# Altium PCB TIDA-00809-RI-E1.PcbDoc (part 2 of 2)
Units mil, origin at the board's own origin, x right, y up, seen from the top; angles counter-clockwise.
Board outline 5400 x 1000 mil, 2 copper layers (Top Layer, Bottom Layer), stack 62 mil thick; 167 components, 75 nets, 354 pads, 72 vias.
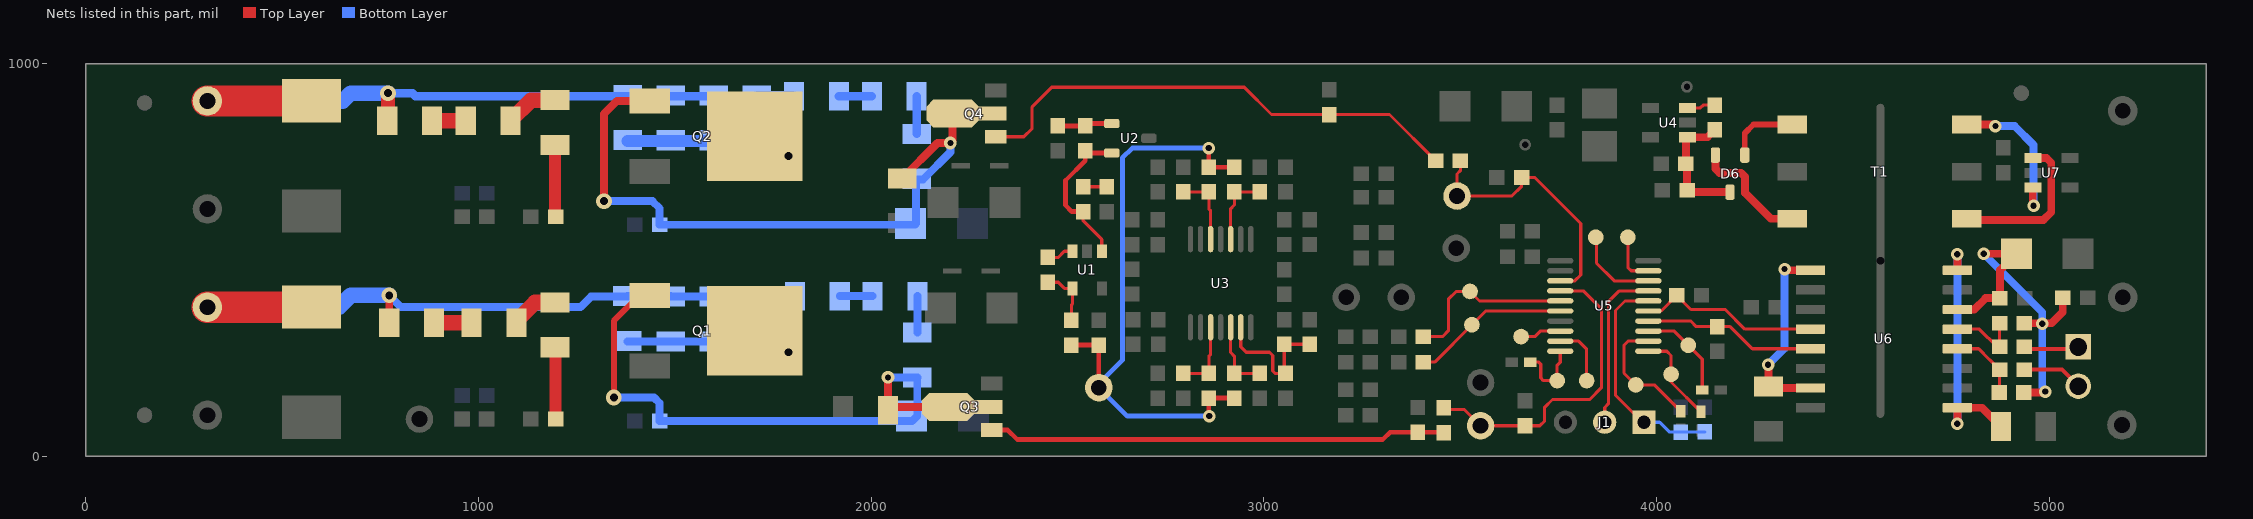
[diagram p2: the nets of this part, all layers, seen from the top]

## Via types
v1: diameter 32, hole 16, Top Layer to Bottom Layer, tented both sides, 61 vias
v2: diameter 40, hole 20, Top Layer to Bottom Layer, tented both sides, 11 vias

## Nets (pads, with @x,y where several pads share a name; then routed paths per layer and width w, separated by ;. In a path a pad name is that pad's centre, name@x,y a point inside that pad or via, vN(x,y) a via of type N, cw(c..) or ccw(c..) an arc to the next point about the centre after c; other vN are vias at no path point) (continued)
NetC7_2: C7.2 R32.2 R34.2 U3.13 | length 355
  Top Layer w8: U3.13@2941.18,328.78 2941.18,278.82 2955,265 3014.43,265 3022.7,256.73 3022.7,217.3 3028.5,211.5 R34.2@3055,211.5 3052,214.5 R32.2@3052,285.5 C7.2@3117,285.5
NetC21_1: C21.1 J1.1 R60.1 U5.16 | length 585.2
  Top Layer w8: J1.1@3973,78 3966,85 3895.5,155.5 3895.5,371.5 3919.8,395.8 U5.16@3979.2,395.8
  Bottom Layer w8: J1.1@3968,87 4008,87 4033.31,61.69 C21.1@4061.3,61.69 4062.11,62.5 R60.1@4123,62.5
NetC22_2: C22.2 D8.1 Q2.G Q4.2 Q4.4 R12.2 R62.2 | length 1688.1
  Top Layer w20: v2(1320,650) 1320,872.13 1352.64,904.76 Q2.G@1436.14,904.76 ; R12.2@2079,708.09 2168.91,798 v1(2202,798) 2207.57,803.57 Q4.4@2207.57,873
  Bottom Layer w12: D8.1@2114.51,593 D8.1@2116,594.49
  Bottom Layer w20: v2(1320,650) 1443,650 1461.5,631.5 C22.2@1461.5,590 2111.51,590 2114.51,593 2114.51,705.42 2132.42,705.42 2202,775 v1(2202,798)
NetC23_2: C23.2 D7.1 Q1.G Q3.2 Q3.4 R11.2 R61.1 | length 1591.1
  Top Layer w15: v2(1345,150) 1345,345 1409.76,409.76 Q1.G@1436.14,409.76
  Top Layer w20: v1(2043,201) 2043.09,200.91 R11.2@2043.09,117 2052.09,126 Q3.4@2196.57,126 ; Q3.4@2170,135 Q3.4@2204.57,135
  Bottom Layer w20: v2(1345,150) 1447,150 1461.5,135.5 C23.2@1461.5,90 2104.53,90 2117.53,103 R61.1@2117.53,200.44 ; v1(2043,201) 2116.98,201 R61.1@2117.53,200.44 ; R61.1@2118,200.91 R61.1@2117.53,200.44
NetD1_2: D1.2 R1.1 R66.1 R67.2 R70.2 R71.2 R73.2 TP1.1 | length 1850.3
  Top Layer w22: R1.1@767.91,855 R1.1@770,857.09 ; R1.1@772.91,860 R1.1@777.91,855
  Top Layer w35: R1.1@770,857.09 v2(770,925)
  Top Layer w80: TP1.1@310,905 574.51,905 D1.2@575,905.49
  Bottom Layer w22: v2(770,925) 832.09,925 840,917.09 1707,917.09 R67.2@1709,919.09 1801.83,919.09 R66.1@1803.91,917
  Bottom Layer w40: TP1.1@310,905 655,905 675,925 v2(770,925)
NetD2_2: D2.2 R2.1 R65.1 R68.2 R69.2 R72.2 R74.2 TP3.1 | length 1979.1
  Top Layer w20: R2.1@772.91,340 v2(772.91,410)
  Top Layer w80: TP3.1@310,380 574.51,380 D2.2@575,380.49
  Bottom Layer w20: v2(772.91,410) 802.91,380 1260,380 1287.09,407.09 R72.2@1490,407.09 ; R74.2@1379,408.09 1489,408.09 R72.2@1490,407.09 ; R65.1@1805.91,408 1805.83,408.09 R68.2@1709,408.09 1708,407.09 R69.2@1600,407.09 R72.2@1490,407.09
  Bottom Layer w40: TP3.1@310,380 645,380 675,410 v2(772.91,410)
NetD6_1: D6.1 T1.4 | length 185.6
  Top Layer w15: D6.1@4224.72,767.27 4224.72,823 4246.72,845 T1.4@4345.5,845
NetD6_2: D6.2 T1.6 | length 307.2
  Top Layer w20: D6.2@4149.91,767.27 4149.91,732.43 4160.32,722.02 4215.32,722.02 4225.32,712.02 4225.32,671.02 4291.34,605 T1.6@4345.5,605
NetJ1_2: J1.2 U5.17 | length 430.1
  Top Layer w8: J1.2@3868,87 3868,124.5 3877.5,134 3877.5,393.5 3905.39,421.39 U5.17@3979.2,421.39 ; J1.2@3873,78 J1.2@3877.5,82.5
NetL1_2: L1.2 U6.1 U6.7 | length 492.6
  Top Layer w20: v1(4284,233) 4285,232 L1.2@4285,178.09 4289.09,174 U6.7@4391.99,174 ; v1(4326,477) 4329,474 U6.1@4391.99,474
  Bottom Layer w20: v1(4284,233) 4326,275 v1(4326,477)
NetL2_1: L2.1 U6.9 U6.16 | length 650.9
  Top Layer w20: v1(4766,83) U6.9@4766.01,124 4828.91,124 L2.1@4876.91,76 L2.1@4876.91,82.09 ; U6.16@4766.01,474 v1(4766,515)
  Bottom Layer w20: v1(4766,83) v1(4766,515)
NetQ1_D: Q1.D R68.1 R69.1 R72.1 R74.1 | length 421.6
  Bottom Layer w20: R74.1@1380,292.91 R72.1@1490,292.91 R69.1@1600,292.91 1710,292.91 1762.09,292.91 v2(1790,265)
NetQ2_D: Q2.D R67.1 R70.1 R71.1 R73.1 | length 532.6
  Top Layer w30: Q2.D@1703.86,815 1753.86,765 v2(1790,765)
  Bottom Layer w30: R73.1@1380,802.91 1490,802.91 1600,802.91 1710,802.91 1747.91,765 v2(1790,765)
NetQ3_1: Q3.1 R42.2 R44.2 | length 1169.2
  Top Layer w12: Q3.1@2306.8,66.94 2348.06,66.94 2372.03,42.97 3302.97,42.97 3321.5,61.5 R42.2@3392,61.5 3457,61.5 R44.2@3458,60.5
NetQ4_1: Q4.1 R35.2 R43.2 | length 1281.6
  Top Layer w8: Q4.1@2317.8,813.94 2388.94,813.94 2410,835 2410,890 2460,940 2950,940 3019.5,870.5 R35.2@3167,870.5 3320,870.5 R43.2@3437.5,753
NetR1_2: R1.2 R5.1 | length 85.8
  Top Layer w40: R1.2@882.09,855 R5.1@967.91,855
NetR2_2: R2.2 R6.1 | length 95.8
  Top Layer w40: R2.2@887.09,340 R6.1@982.91,340
NetR5_2: R5.2 R9.1 | length 134.5
  Top Layer w40: R5.2@1082.09,855 1134.17,907.09 R9.1@1195,907.09
NetR6_2: R6.2 R10.1 | length 117.4
  Top Layer w40: R6.2@1097.09,345 1144.17,392.09 R10.1@1195,392.09
NetR7_1: R7.1 R9.2 | length 183.5
  Top Layer w30: R9.2@1195,792.91 1195,611.5 R7.1@1196.5,610
NetR8_1: R8.1 R10.2 | length 183.5
  Top Layer w30: R10.2@1195,277.91 1196.5,276.42 R8.1@1196.5,95
NetR13_1: R13.1 U1.3 | length 69.1
  Top Layer w8: R13.1@2450,506.5 2476.5,506.5 2492.24,522.24 U1.3@2512.6,522.24
NetR13_2: R13.2 R15.1 U1.4 | length 151.5
  Top Layer w8: R13.2@2450,443.5 2476.5,443.5 2492.24,427.76 U1.4@2512.6,427.76 2512.6,387.6 2510,385 R15.1@2510,346.5
NetR14_2: R14.2 R17.1 U2.1 | length 140.2
  Top Layer w12: R14.2@2475,841.5 R17.1@2545,841.5 2550.91,847.4 U2.1@2612.76,847.4
NetR16_1: R16.1 R17.2 U1.1 U2.2 | length 402.1
  Top Layer w8: R16.1@2540,623.5 2540,600 2587.4,552.6 U1.1@2587.4,522.24
  Top Layer w12: R16.1@2540,623.5 2511.5,623.5 2495,640 2495,702.51 2545,752.51 R17.2@2545,778.5 2550.91,772.6 U2.2@2612.76,772.6
NetR16_2: R16.2 R18.2 | length 60
  Top Layer w8: R16.2@2540,686.5 R18.2@2600,686.5
NetR23_2: R23.2 R25.2 U3.10 | length 184.1
  Top Layer w8: R23.2@2795,211.5 R25.2@2860,211.5 2860,255 2864.41,259.41 U3.10@2864.41,328.78
NetR24_2: R24.2 R26.2 U3.5 | length 187.1
  Top Layer w8: R24.2@2795,673.5 R26.2@2860,673.5 2860,630 2864.41,625.59 U3.5@2864.41,553.19
NetR27_2: R27.2 R30.2 U3.12 | length 186.2
  Top Layer w8: U3.12@2915.59,328.78 2915.59,264.41 2925,255 R27.2@2925,211.5 R30.2@2990,211.5
NetR28_2: R28.2 R29.1 U3.3 | length 189.2
  Top Layer w8: U3.3@2915.59,553.19 2915.59,630.59 2925,640 R28.2@2925,673.5 R29.1@2990,673.5
NetR40_2: R40.2 TP12.1 U5.5 | length 452.8
  Top Layer w8: R40.2@3406.5,305 3455,305 3470,320 3470,400 3490,420 TP12.1@3525,420 3549.2,395.8 U5.5@3754.8,395.8
NetR41_2: R41.2 TP13.1 U5.6 | length 402.2
  Top Layer w8: R41.2@3406.5,240 3435,240 TP13.1@3530,335 3565.2,370.2 U5.6@3754.8,370.2
NetR46_2: R46.2 TP17.1 U5.10 | length 186.6
  Top Layer w8: R46.2@3678.62,240 3700,240 3705,235 3705,200 3712,193 TP17.1@3747,193 3747,232 3754.8,239.8 U5.10@3754.8,267.84 ; U5.10@3747,267.84 U5.10@3747,268
NetR48_1: R48.1 U4.3 | length 72.7
  Top Layer w8: U4.3@4078.56,887.43 4111.52,887.43 4118.61,894.52 R48.1@4148.32,894.52
NetR50_2: R50.2 TP22.1 U5.12 | length 330.1
  Top Layer w8: TP22.1@3947,182 TP22.1@3951.85,182 ; U5.12@3979.2,293.43 3927.43,293.43 3917,283 3917,212 3941,188 3945.85,188 TP22.1@3951.85,182 ; R50.2@4062,114.62 3994.62,182 TP22.1@3951.85,182 ; R50.2@4062.31,114.93 R50.2@4064,113.24
NetR51_2: R51.2 TP24.1 U5.13 | length 245.4
  Top Layer w8: U5.13@3979.2,319.02 4044.98,319.02 TP24.1@4081,283 4116.38,247.62 R51.2@4116.38,169
NetR53_2: R53.2 TP23.1 U5.11 | length 237.5
  Top Layer w8: U5.11@3979.2,267.84 4026.16,267.84 4037,257 TP23.1@4037,209 4037,189.24 R53.2@4113,113.24
NetR54_1: R54.1 R55.1 U6.13 | length 186.2
  Top Layer w8: U6.13@4766.01,324 4822,324 4867.16,278.84 R55.1@4873.5,278.84 R54.1@4873.5,338.84
NetR56_1: R56.1 R57.1 U6.12 | length 187.9
  Top Layer w8: U6.12@4766.01,274 4820.16,274 4848.02,246.14 4848.2,246.14 R56.1@4873.5,220.84 4873.5,163.84 R57.1@4872.5,162.84
NetR61_2: R61.2 R63.1 | length 92.9
  Bottom Layer w20: R61.2@2118,315.09 2118.09,315.17 R63.1@2118.09,408
NetR62_1: R62.1 R64.2 | length 95.9
  Bottom Layer w22: R62.1@2116,821.09 2116.09,821.17 R64.2@2116.09,917
NetR63_2: R63.2 R65.2 | length 83.8
  Bottom Layer w20: R65.2@1920.09,408 R63.2@2003.91,408
NetR64_1: R64.1 R66.2 | length 83.8
  Bottom Layer w22: R66.2@1918.09,917 R64.1@2001.91,917
NetT1_1: T1.1 U7.1 | length 401.7
  Top Layer w20: T1.1@4790.5,605 4793.5,602 4985,602 5005,622 5005,747.83 4993.43,759.4 U7.1@4958,759.4
NetT1_3: T1.3 U7.3 | length 393.5
  Top Layer w20: T1.3@4790.5,845 4859,845 v1(4863,841) ; U7.3@4958,684.6 4958,640 v1(4960,638)
  Bottom Layer w20: v1(4863,841) 4912,841 4960,793 v1(4960,638)
NetTP16_1: TP16.1 U5.8 | length 105.6
  Top Layer w8: TP16.1@3655,305 3690,305 3704.02,319.02 U5.8@3754.8,319.02
NetTP18_1: TP18.1 U5.9 | length 155.7
  Top Layer w8: U5.9@3754.8,293.43 3801.57,293.43 3822,273 TP18.1@3822,193
NetTP19_1: TP19.1 U5.18 | length 216.9
  Top Layer w8: TP19.1@3847,558 3847,491.98 3892,446.98 U5.18@3979.2,446.98
NetTP21_1: TP21.1 U5.19 | length 132.7
  Top Layer w8: TP21.1@3927,558 3927,481 3935.43,472.57 U5.19@3979.2,472.57
PWM_0: R43.1 R45.1 TP11.1 U5.3 | length 678.8
  Top Layer w8: R43.1@3500.5,753 3500.5,727.5 3492,719 TP11.1@3492,663 3631.5,663 3656.5,688 R45.1@3656.5,710 3690,710 3807,593 3807,461.98 3792,446.98 U5.3@3754.8,446.98
PWM_1: R44.1 R47.1 TP15.1 U5.4 | length 804.9
  Top Layer w8: R44.1@3457,119.5 3510.5,119.5 TP15.1@3552,78 3703,78 3715,90 3715,125 3735,145 3830,145 3859.5,174.5 3859.5,375.5 3813.61,421.39 U5.4@3754.8,421.39
SCL: R52.1 U5.14 U6.5 | length 442
  Top Layer w8: U5.14@3979.2,344.61 4087,344.61 4101.12,330.5 R52.1@4155,330.5 4187.5,330.5 4244,274 U6.5@4391.99,274
SCL_ISO: J2.2 R56.2 | length 154.9
  Top Layer w10: R56.2@4936.5,220.84 5032,220.84 J2.2@5074,178.84
SDA: R49.1 U5.15 U6.4 | length 464.9
  Top Layer w8: U5.15@3979.2,370.2 4011.71,370.2 R49.1@4051.5,410 4087.5,374 4175,374 4225,324 U6.4@4391.99,324
SDA_ISO: J2.1 R55.2 | length 140.1
  Top Layer w10: R55.2@4936,273.84 5069,273.84 J2.1@5074,278.84
VCC_0: C16.1 C17.1 D6.3 R48.2 U4.1 | length 326.7
  Top Layer w20: R48.2@4148.32,831.53 4129.41,812.62 U4.1@4078.56,812.62 4074.81,808.88 C16.1@4074.81,745.02 4077.81,742.02 C17.1@4077.81,678.02 4083.06,672.78 D6.3@4187.32,672.78
VCC_ISO: C19.1 D9.1 R54.2 R57.2 R58.1 U6.14 | length 951.9
  Top Layer w20: U6.14@4766.01,374 4809,374 4838,403 C19.1@4874.5,403 4874.5,474.24 D9.1@4916.26,516 v1(4833,516) ; R57.2@4935.5,162.84 4987.84,162.84 v1(4990,165) ; R54.2@4936.5,338.84 5005.84,338.84 5034.5,367.5 R58.1@5034.5,404
  Bottom Layer w20: v1(4833,516) 4982,367 v1(4982,337.84) 4982,173 v1(4990,165)
VREF_PH: C1.2 R15.2 R25.1 R26.1 R27.1 R28.1 TP6.1 | length 1553.3
  Top Layer w12: R15.2@2510,283.5 C1.2@2580,283.5 TP6.1@2580,175 ; R25.1@2860,148.5 2860,103.63 v1(2860.92,102.71) ; v1(2860,785) R26.1@2860,736.5 R28.1@2925,736.5 ; R25.1@2860.92,148.5 R27.1@2925,148.5
  Bottom Layer w12: v1(2860,785) 2665,785 2640,760 2640,245 2580,185 TP6.1@2580,175 2652.29,102.71 v1(2860.92,102.71)
pads on no net: FID1.1 FID2.1 FID3.1 FID4.1 FID5.1 FID6.1 U4.4 U6.2 U6.6 U6.8 U6.10 U6.11 U6.15

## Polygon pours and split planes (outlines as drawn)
GND on Bottom Layer "Multi-Layer-No Net" (solid, remove dead copper, pour order 9): 2405,950 2430,975 2470,975 4346,975 4378,943 4378,540 4383,535 4409,535 4430,514 4430,60 4400,30 4205,30 4195,30 2440,30 2405,65 2405,945

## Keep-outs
Keep-Out Layer:
  pour cut-out: 4380,977 4380,540 4430,540 4430,27 4728,27 4728,540 4755,540 4755,977
  lines w3.94: 50,25 5382,25 5382,983 50,983 50,25
  text ".Layer_Name" at 297,-1308.49 h60

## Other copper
Top Layer:
  text ".Layer_Name" at 297,-1308.49 h60
Bottom Layer:
  text ".Layer_Name" at 297,-1308.49 h60

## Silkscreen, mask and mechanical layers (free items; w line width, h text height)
Top Overlay:
  drawing of 213 lines, arcs and shapes, not listed
  text "GND" at 4011,970 h35
  text "GND_ISO" at 5296,766 h50 r90
  text "PWM_0" at 3445,590 h30
  text "A" at 2152,543 h35
  text "K" at 2377,543 h35
  text "A" at 5184,523 h30
  text "CH-1" at 365,520 h35
  text "CH-2" at 365,460 h35
  text "B" at 1970,370 h35
  text "+3.3V" at 5296,347 h50 r90
  text "A" at 2146,276 h35
  text "K" at 2363,258 h35
  text "B" at 3875,155 h35
  text "GND" at 785,65 h35 r90
  text "A" at 4761,53 h30
  text "GND_ISO" at 5318,23 h50 r90
  text "PWM_1" at 3620,10 h30
  text ".Layer_Name" at 297,-1308.49 h60
Bottom Overlay:
  lines w20: 5,500 2274,500 ; 2635,35 2635,236 2626,245 2564,307 2345,307 2345,500 2580,500 2580,720 2640,720 2640,970
  text "K" at 2019,639 h35 r180
  text "A" at 2334,576 h35
  text "TIDA-00809-BI" at 1216,404 h60
  text "REV :" at 1113,297 h60
  text ".PCB_Rev" at 809,293 h60
  text "K" at 2026,158 h35 r180
  text "A" at 2324,87 h35
  text ".Layer_Name" at 297,-1308.49 h60
Top Paste:
  text ".Layer_Name" at 297,-1308.49 h60
Bottom Paste:
  text ".Layer_Name" at 297,-1308.49 h60
Top Solder:
  text ".Layer_Name" at 297,-1308.49 h60
  text ".Layer_Name" at 297,-1308.49 h60
Bottom Solder:
  text ".Layer_Name" at 297,-1308.49 h60
Drill Guide:
  text ".Layer_Name" at 297,-1308.49 h60
M1 Board Outline:
  the board outline again, w10
M2 Board Dimensions:
  rectangle: 314.5,-455 689.5,-330
  rectangle: 189.5,-330 314.5,-205
  lines w7: 189.5,-330 1189.5,-330 ; 314.5,-455 314.5,-205 ; 439.5,-455 439.5,-205 ; 689.5,-455 689.5,-205 ; 939.5,-455 939.5,-205 ; 189.5,-455 189.5,-205 1189.5,-205 1189.5,-455 189.5,-455
  lines w10: 189.5,-520 189.5,-500 ; 249.5,-530 189.5,-510 ; 249.5,-490 189.5,-510 ; 413.58,-510 189.5,-510 ; 965.42,-510 1189.5,-510 ; 1129.5,-530 1189.5,-510 ; 1129.5,-490 1189.5,-510 ; 1189.5,-520 1189.5,-500
  text "1000 (mil)" at 423.58,-545.99 h60
M3 3D STEP Top:
  text ".Layer_Name" at 297,-1308.49 h60
M4 3D STEP Bottom:
  text ".Layer_Name" at 297,-1308.49 h60
M5 Assembly Top:
  circle w6: c4104,810 r7.07
  circle w6: c2652.93,845 r7.07
  circle w6: c2587.93,490 r7.07
  circle w6: c4699,600 r20.23
  circle w6: c1381,411 r12
  circle w6: c1389,906 r12
  circle w6: c2268.64,810 r13.36
  circle w6: c2269,66 r12
  circle w6: c3968.92,85 r6.08
  circle w6: c4225,788 r5.1
  circle w10: c4457,477 r13
  lines w3.94: 2094,473 2107,473 ; 2100,490 2107,483 ; 2112,455 2107,460 2107,483 ; 2116,473.5 2132.5,473.5 ; 2136.5,492 2141.5,487 2141.5,464 ; 2138,740 2151,740 ; 2144,757 2151,750 ; 2148.5,457 2141.5,464 ; 2154.5,474 2141.5,474 ; 2156,722 2151,727 2151,750 ; 2160,740.5 2176.5,740.5 ; 2180.5,759 2185.5,754 2185.5,731 ; 2192.5,724 2185.5,731 ; 2198.5,741 2185.5,741 ; 2107,473 2116,464 2116,483 2116,482 2107,473 ; 2107,473 2107,483 ; 2141.5,464 2141.5,474 ; 2141.5,474 2132.5,465 2132.5,464 2132.5,483 2141.5,474 ; 2151,740 2151,750 ; 2151,740 2160,749 2160,750 2160,731 2151,740 ; 2185.5,731 2185.5,741 ; 2185.5,741 2176.5,750 2176.5,731 2176.5,732 2185.5,741
  lines w6: 4941.02,759.88 ccw(c4934,759) 4941.07,759 ; 5075.54,284.54 ccw(c5072,281) 5077,281 ; 4436,98 4436,507 4722,507 4722,98 4436,98
  lines w10: -572,-1380.17 6028,-1380.17 ; -572,-1176.83 6030,-1176.83 ; -572,-973.5 -572,-1583.5 3433,-1583.5 6030,-1583.5 6030,-973.5 -571.5,-973.5 -571.5,-1583.5 1004,-1583.5 ; 1893,-1583.5 1893,-973.5 ; 3160,-1176.83 3160,-973.5 ; 4000,-1176.83 4000,-973.5 ; 4622,-1590 4622,-1387.17
  text "A" at 3424,943 h25
  text "K" at 3723,940 h25
  text "K" at 4871,588 h25
  text "A" at 5083,585 h25
  text "A" at 2155,552 h25
  text "K" at 2386,550 h25
  text "K" at 2413,360 h25
  text "A" at 2108,354 h25
  text "COMPONENTS MARKED 'DNP' SHOULD NOT BE POPULATED." at 873.5,-768.5 h25
  text "ASSEMBLY VARIANT:" at 873,-884 h25
  text ".VariantName" at 1909,-884 h25
  text "PCB VIEWED FROM TOP SIDE" at -508.5,-1105.67 h25
  text "BOARD #:" at 1968,-1105.67 h25
  text ".PRJ_Number" at 2513.5,-1105.67 h25
  text "REV:" at 3358,-1105.67 h25
  text ".PCB_Rev" at 3649.5,-1105.67 h25
  text "SVN REV:" at 4196,-1105.67 h25
  text ".VersionControl_RevNumber" at 4702,-1105.67 h25
  text "TID #:" at 1963,-1276 h30
  text ".PRJ_Number" at 2165.5,-1277 h30
  text ".Layer_Name" at 220,-1285 h25
  text "LAYER NAME =" at -396,-1293 h30
  text "IGNORE ->" at 3645,-1293 h25
  text "PLOT NAME =" at -508.5,-1514.34 h25
  text ".plot_File_Name" at 297,-1514.34 h25
  text "GENERATED    :" at 1970,-1514.34 h25
  text ".Print_Date" at 2839.5,-1514.34 h25
  text ".Print_Time" at 3568.5,-1514.34 h25
  text "TEXAS INSTRUMENTS" at 4833,-1514.34 h25
M6 Assembly Bottom:
  lines w10: -572.5,-1177.33 6029.5,-1177.33 ; -570.5,-1380.67 6029.5,-1380.67 ; 835.5,-1590.5 835.5,-1387.67 ; 1457.5,-1177.33 1457.5,-974 ; 2297.5,-1177.33 2297.5,-974 ; 3564.5,-1584 3564.5,-974 ; 4453.5,-1584 6029,-1584 6029,-974 -572.5,-974 -572.5,-1584 2024.5,-1584 6029.5,-1584 6029.5,-974
  text "K" at 2021,606 h25 r180
  text "A" at 2307,577 h25
  text "K" at 2023,121 h25 r180
  text "A" at 2310,90 h25
  text "COMPONENTS MARKED 'DNP' SHOULD NOT BE POPULATED." at 5822,-768 h25
  text ".VariantName" at 4778,-884 h25
  text "ASSEMBLY VARIANT:" at 5817,-884 h25
  text ".VersionControl_RevNumber" at 755.5,-1106.17 h25
  text "SVN REV:" at 1261.5,-1106.17 h25
  text ".PCB_Rev" at 1808,-1106.17 h25
  text "REV:" at 2099.5,-1106.17 h25
  text ".PRJ_Number" at 2944,-1106.17 h25
  text "BOARD #:" at 3489.5,-1106.17 h25
  text "PCB VIEWED FROM BOTTOM SIDE" at 5966,-1106.17 h25
  text "TID #:" at 3486,-1260 h30
  text ".PRJ_Number" at 3242.5,-1266 h30
  text ".Layer_Name" at 5431,-1266.33 h30
  text "IGNORE ->" at 1873,-1270 h25
  text "LAYER NAME =" at 5898,-1270.33 h30
  text "TEXAS INSTRUMENTS" at 624.5,-1514.84 h25
  text ".Print_Time" at 1889,-1514.84 h25
  text ".Print_Date" at 2618,-1514.84 h25
  text "GENERATED    :" at 3487.5,-1514.84 h25
  text ".plot_File_Name" at 5160.5,-1514.84 h25
  text "PLOT NAME =" at 5966,-1514.84 h25
M9 Title Sheet:
  drawing of 57 lines, arcs and shapes, not listed
  text "1" at 459.84,7586.5 h70
  text "2" at 2955.5,7586.5 h70
  text "3" at 5444.84,7586.5 h70
  text "4" at 7951.51,7586.5 h70
  text "5" at 10450.5,7586.5 h70
  text "6" at 12955.5,7586.5 h70
  text "A" at -696.5,6443.5 h70
  text "A" at 14103.5,6443.5 h70
  text "B" at -696.5,4063.5 h70
  text "B" at 14103.5,4063.5 h70
  text "C" at -696.5,1688.5 h70
  text "C" at 14103.5,1688.5 h70
  text "PROJECT TITLE:" at 11063.5,-172.5 h45
  text ".PRJ_Title" at 11113.5,-305.83 h70
  text "DESIGNED FOR:" at 11063.5,-473.5 h45
  text ".PRJ_Customer" at 11113.5,-613.5 h70
  text "D" at -696.5,-681.5 h70
  text "D" at 14103.5,-681.5 h70
  text "FILE NAME:" at 11063.5,-773.5 h45
  text ".PCB_File_Name_No_Path" at 11113.5,-893.5 h70
  text "Texas Instruments (TI) and/or its licensors do not warrant the accuracy or completeness of this specification" at 6094,-1055.34 h45
  text "ENGINEER:" at 11063.5,-1063.5 h45
  text "LAYOUT BY:" at 12568.5,-1063.5 h45
  text "or any information contained therein. TI and/or its licensors do not warrant that this design will meet" at 6049.01,-1168 h45
  text ".PRJ_Engineer" at 11113.5,-1218.49 h70
  text ".PCB_Layout" at 12619,-1218.49 h70
  text "the specifications, will be suitable for your application or fit for any particular purpose, or will operate in" at 6049.01,-1280.67 h45
  text "ALTIUM DESIGNER VERSION:" at 12568.5,-1373.5 h45
  text "an implementation. TI and/or its licensors do not warrant that the design is production worthy. You should" at 6049.01,-1393.33 h45
  text "completely validate and test your design implementation to confirm the system functionality for your application." at 6094,-1506 h45
  text ".print_Scale" at 11113.5,-1506.83 h70
  text ".Application_BuildNumber" at 12619,-1506.83 h70
  text "1" at 459.84,-1713.5 h70
  text "2" at 2955.5,-1713.5 h70
  text "3" at 5444.84,-1713.5 h70
  text "4" at 7951.51,-1713.5 h70
  text "5" at 10450.5,-1713.5 h70
  text "6" at 12955.5,-1713.5 h70
M10 Fab Notes:
  drawing of 228 lines, arcs and shapes, not listed
  text "DESIGN INFORMATION" at 12101.02,6360 h60
  text "(REFER ALSO ARRAY/PANEL PROFILING INFORMATION)" at 11739.46,6198.29 h60
  text "BOARD SIZE" at 11053.46,6194 h60
  text "5400MIL" at 11515.78,6066.18 h60
  text "X" at 12021.46,6066.18 h60
  text "1000MIL" at 12252.78,6066.18 h60
  text "Number of Layers :" at 11456.46,5869 h60
  text "2" at 12551.27,5859 h60
  text "MIN. TRACK WIDTH:" at 11456.46,5730 h60
  text "8" at 12552.7,5730 h60
  text "MIL" at 12707.46,5730 h60
  text "MIN. CLEARANCE:" at 11456.46,5598 h60
  text "MIL" at 12707.46,5598 h60
  text "8" at 12545,5597 h60
  text "MIN. VIA PAD SIZE:" at 11456.46,5466 h60
  text "30" at 12522.71,5466 h60
  text "MIL" at 12707.46,5466 h60
  text "0.177mm (7MIL)" at 12151.46,5324.29 h60
  text "MINIMUM ANNULAR RING" at 11127.23,5320 h60
  text "EXTERNAL" at 12859.46,5320 h60
  text "PER" at 11327.23,5202 h60
  text "IPC-D-275 CLASS 2 LEVEL C" at 11547.23,5202 h60
  text "MIL, HOLES" at 13035.46,5089.71 h60
  text "+/-" at 12643,5089 h60
  text "+/-" at 13497,5089 h60
  text "REGISTRATION TOLERANCES:" at 11127.23,5084 h60
  text "METAL" at 12327,5084 h60
  text "5" at 12903.2,5084 h60
  text "3" at 13736.2,5084 h60
  text "MIL" at 13852.46,5084 h60
  text "MATERIAL:" at 11052.46,4874.54 h60
  text "FR4" at 13475,4740 h60
  text "FR-4 High Tg" at 12038.9,4734.21 h60
  text "FR-408" at 11473.46,4725.64 h60
  text "X" at 12774.46,4726 h60
  text "OTHER" at 12961.46,4725.64 h60
  text "63 MIL (1.6mm) +/-10%" at 11793.56,4562.92 h60
  text "THICKNESS:" at 11127.23,4558.64 h60
  text "X" at 11665.4,4558.64 h60
  text "OTHER" at 13078.46,4558.64 h60
  text "TOLERANCE:" at 11127.23,4400.64 h60
  text "X" at 11966.53,4400.64 h60
  text "ANSI IPC-6012 TYPE 3 CLASS 2" at 12153.48,4400.64 h60
  text "OTHER +/-" at 12153.46,4244.64 h60
  text "BOW & TWIST:" at 11127.23,4087.64 h60
  text "X" at 11966.53,4087.64 h60
  text "ANSI IPC-6012 TYPE 3 CLASS 2" at 12153.48,4087.64 h60
  text "OTHER +/-" at 12153.46,3929.13 h60
  text "COPPER THICKNESS (FINISHED):" at 11052.46,3793.64 h60
  text "1.4MIL (1oz)" at 11932.46,3640.92 h60
  text "2MIL (1.4oz)" at 12699.46,3640.92 h60
  text "2.8MIL (2oz)" at 13426.46,3640.92 h60
  text "OUTER:" at 11409.46,3636.64 h60
  text "X" at 11804,3636 h60
  text "1.4MIL (1oz)" at 11932.46,3483.92 h60
  text "2.8MIL (2oz)" at 12699.46,3483.92 h60
  text "N/A" at 13426,3484.29 h60
  text "INNER SIGNAL:" at 11120.38,3479.64 h60
  text "DRILLING:" at 11052.46,3340.64 h60
  text "REFERENCE:" at 11127.23,3223.64 h60
  text "X" at 11775.46,3223.64 h60
  text "AS SHOWN" at 11962.46,3223.64 h60
  text "X" at 12676.46,3223.64 h60
  text "NC_DRILL FILES" at 12813.46,3223.64 h60
  text "PTH MIN COPPER THICKNESS:" at 11127.23,3065.64 h60
  text "X" at 12477.46,3065.64 h60
  text "1MIL" at 12614.46,3065.64 h60
  text "OTHER" at 13111.46,3065.64 h60
  text "BOARD FINISH:" at 11052.46,2906.64 h60
  text "SILKSCREEN:" at 11207.68,2788.64 h60
  text "X" at 12156.46,2788.64 h60
  text "TOP" at 12282.46,2788.64 h60
  text "X" at 12666.46,2788.64 h60
  text "BOTTOM" at 12793.46,2788.64 h60
  text "SILKSCREEN COLOR:" at 11207.68,2621.64 h60
  text "X" at 12155.42,2621.64 h60
  text "WHITE" at 12282.46,2621.64 h60
  text "OTHER" at 12793.46,2621.64 h60
  text "SOLDER RESIST COLOR:" at 11207.68,2451.64 h60
  text "X" at 11775.42,2292.44 h60
  text "GREEN" at 11902.46,2292.44 h60
  text "BLUE" at 12493.46,2292.44 h60
  text "OTHER" at 13031.46,2292.44 h60
  text "IMMERSION GOLD (ENIG)" at 12113.46,2103.92 h60
  text "ENEPIG" at 13451,2100.64 h60
  text "SURFACE FINISH:" at 11052.46,2099.64 h60
  text "X" at 11926.51,2099.64 h60
  text "IMM. TIN/SILVER OR EQUIV" at 11382,1942.64 h60
  text "OTHER" at 12813.46,1942.64 h60
  text "ARRAY/PANEL:" at 11052.46,1763.64 h60
  text "CUT AND TRIM PER MECH LAYER 1" at 12113.46,1759.35 h60
  text "N.C. ROUTE" at 12113.46,1607.64 h60
  text "X" at 12792.46,1607.64 h60
  text "V. SCORE" at 12979.46,1607.64 h60
  text "CERTIFICATION:" at 11052.46,1470.64 h60
  text "MATERIALS AND WORKMANSHIP FOR ALL PCBS" at 11777.46,1470.64 h60
  text "TO MEET OR EXCEED THE REQUIREMENTS OF:" at 11777.46,1372.64 h60
  text "X" at 11403.96,1236.13 h60
  text "ANSI IPC-A-600F CLASS ->" at 11542.96,1236.13 h60
  text "X" at 13182.02,1236.13 h60
  text "2" at 13300.96,1236.14 h60
  text "1" at 12985.96,1234.64 h60
  text "3" at 13654.96,1234.64 h60
  text "X" at 11406.02,1076.64 h60
  text "UL 94V-0" at 11542.96,1076.64 h60
  text "X" at 12218.02,1076.64 h60
  text "RoHS" at 12354.96,1076.64 h60
  text "OTHER" at 12999.36,1076.64 h60
  text "PER ORDER" at 13396.42,1076.64 h60
  text "VIA TENTING:" at 12270,943 h60
  text "X" at 13036.29,943.11 h60
  text "ADDITIONAL REQUIREMENTS:" at 11052.46,935.64 h60
  text "YES" at 12819.67,933.92 h60
  text "NO" at 13184.47,928.69 h60
  text "MICROSECTION:" at 11127.23,820.64 h60
  text "YES" at 12032.96,820.64 h60
  text "IMPEDANCE CONTROL:" at 12292,814 h60
  text "YES" at 13276,813 h60
  text "X" at 13818,806 h60
  text "NO" at 13651.47,795.69 h60
  text "REQUIRED" at 12894.46,664.49 h60
  text "BARE BOARD ELEC. TEST:" at 11127.23,661.64 h60
  text "NONE" at 12432.96,661.64 h60
  text "X" at 12767.46,661.64 h60
  text "PER ORDER" at 13486.46,661.64 h60
  text "MANUFACTURER'S UL:" at 11127.23,504.64 h60
  text "RAIL" at 12292.96,500.35 h60
  text "METAL" at 12784.77,500.35 h60
  text "X" at 13160,500 h60
  text "SILK" at 13296.46,500.35 h60
M11 Gerber Information:
  lines w10: -572,-1380.17 6028,-1380.17 ; -572,-1176.83 6030,-1176.83 ; -572,-973.5 -572,-1583.5 3433,-1583.5 6030,-1583.5 6030,-973.5 -571.5,-973.5 -571.5,-1583.5 1004,-1583.5 ; 1893,-1583.5 1893,-973.5 ; 3160,-1176.83 3160,-973.5 ; 4000,-1176.83 4000,-973.5 ; 4622,-1590 4622,-1387.17
  text ".PRJ_Number" at 2444,-1103 h40
  text "ALL ARTWORK VIEWED FROM TOP SIDE" at -508.5,-1105.67 h60
  text "BOARD #:" at 1968,-1105.67 h60
  text "REV:" at 3358,-1105.67 h60
  text ".PCB_Rev" at 3649.5,-1105.67 h60
  text "SVN REV:" at 4196,-1105.67 h60
  text ".VersionControl_RevNumber" at 4702,-1105.67 h60
  text ".PRJ_Number" at 2306.5,-1282 h40
  text "TID #:" at 1941,-1287 h60
  text "LAYER NAME =" at -508.5,-1308.49 h60
  text "PLOT NAME =" at -508.5,-1514.34 h60
  text ".plot_File_Name" at 297,-1514.34 h60
  text "GENERATED    :" at 1970,-1514.34 h60
  text ".Print_Date" at 2839.5,-1514.34 h60
  text ".Print_Time" at 3568.5,-1514.34 h60
  text "TEXAS INSTRUMENTS" at 4833,-1514.34 h60
M12 Stackup:
  lines w6: 11080,7010 13630,7010 ; 11080,7114.4 13630,7114.4 ; 11020,6525 ccw(c11054,6525) 11054,6491 13656,6491 ccw(c13656,6525) 13690,6525 13690,7231 ccw(c13656,7231) 13656,7265 11054,7265 ccw(c11054,7231) 11020,7231 11020,6525
  text "Layer Stack Up Detail for: TIDA-00809-RI-E1" at 11080,7147.1 h57
  text "Layer" at 11080,7075.4 h24
  text "Gerber" at 11975.81,7075.4 h24
  text "Copper" at 12539.33,7075.4 h24
  text "Dielectric" at 13142.04,7075.4 h24
  text "Name" at 11080,7027.4 h24
  text "Document" at 11975.81,7027.4 h24
  text "Thickness" at 12539.33,7027.4 h24
  text "Material" at 13142.04,7027.4 h24
  text "Top Solder Mask" at 11080,6934.44 h34
  text "(.GTS)" at 11975.81,6934.44 h34
  text "Solder Resist" at 13142.04,6934.44 h34
  text "Top Layer" at 11080,6837.69 h34
  text "(.GTL)" at 11975.81,6837.69 h34
  text "1.4mil" at 12539.33,6837.69 h34
  text "FR4" at 13142.04,6789.31 h34
  text "Bottom Layer" at 11080,6740.94 h34
  text "(.GBL)" at 11975.81,6740.94 h34
  text "1.4mil" at 12539.33,6740.94 h34
  text "Bottom Solder Mask" at 11080,6644.19 h34
  text "(.GBS)" at 11975.81,6644.19 h34
  text "Solder Resist" at 13142.04,6644.19 h34
M13 Component Bodies Top:
  text ".Layer_Name" at 297,-1308.49 h60
M14 Component Bodies Bottom:
  text ".Layer_Name" at 297,-1308.49 h60
M15 Courtyards Top:
  text ".Layer_Name" at 297,-1308.49 h60
M16 Courtyards Bottom:
  text ".Layer_Name" at 297,-1308.49 h60
Drill Drawing:
  text ".legend" at 248,2786 h60
  text "Drill Table" at 245,2615 h60
  text "FOR 16MIL DRILL +0/-16MIL" at 259,2495 h60
  text "FOR 20MIL DRILL +0/-20MIL" at 259,2365 h60
  text "FOR PTH DRILL +/-3MIL" at 254,2235 h60
  text "FOR NPTH DRILL +/-2MIL" at 256,2134 h60
  text ".Layer_Name" at 297,-1308.49 h60

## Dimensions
0,0 to 0,1000 on M2 Board Dimensions
0,1000 to 5400,1000 on M2 Board Dimensions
